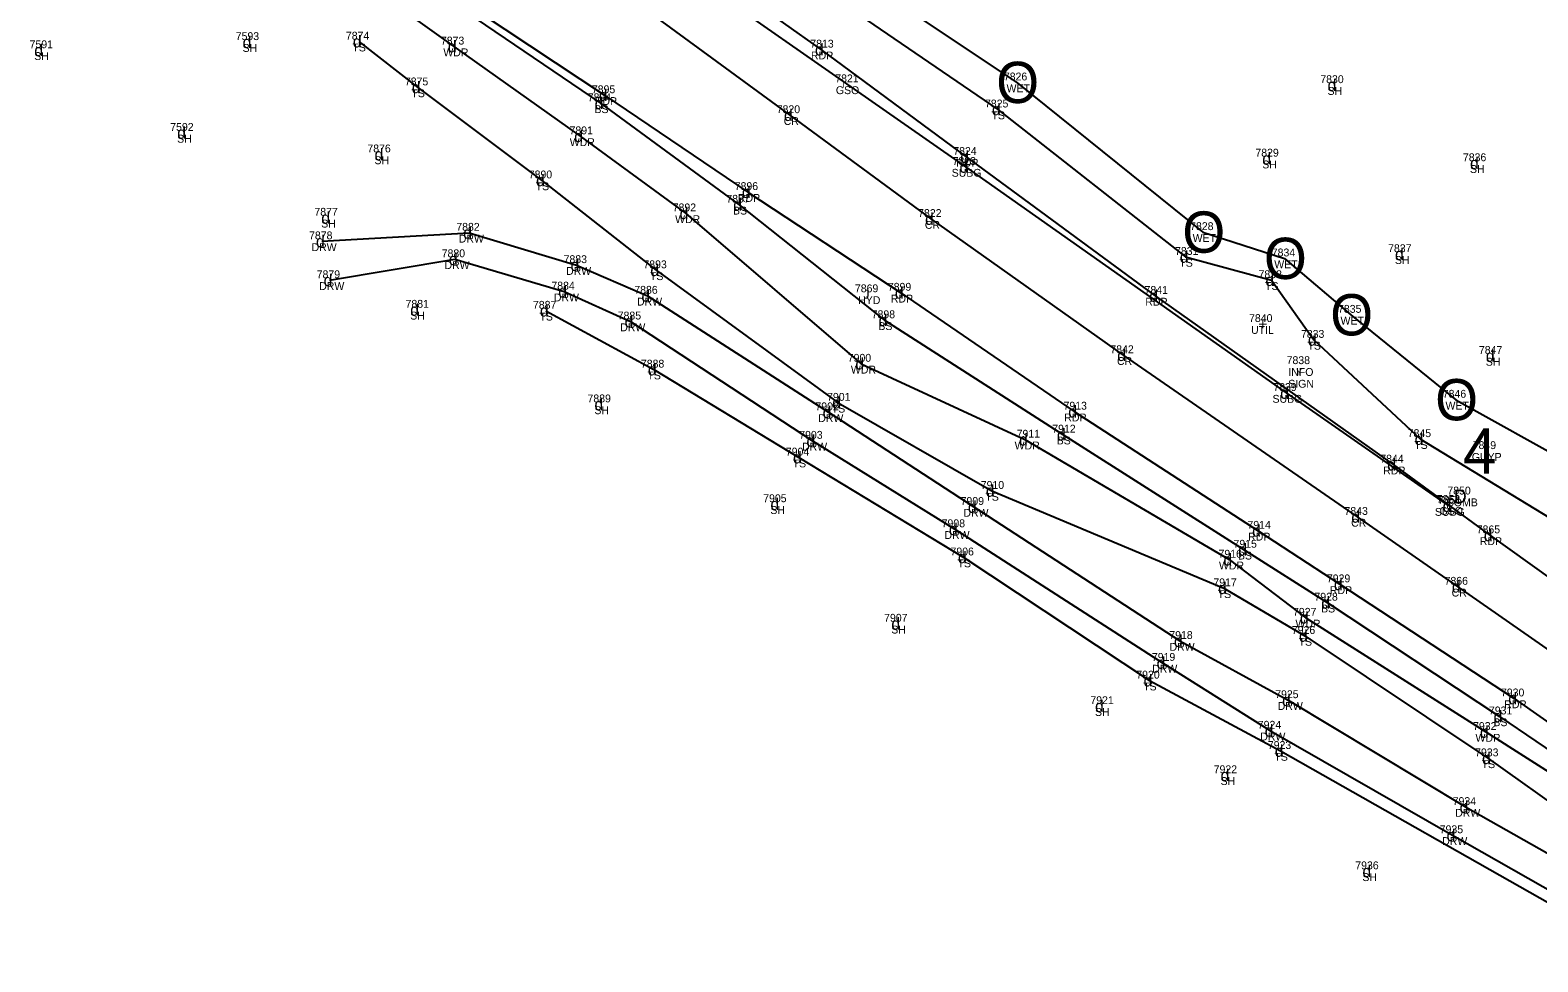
# Model space of a CAD drawing. Extents: x 69415 to 80913, y 7576 to 15059.
# Drawn here: x 76411 to 76794.6, y 13698.5 to 13935.5 of the extents above; entities that cross this region are included whole.
import ezdxf

# ---------------------------------------------------------------- set-up
doc = ezdxf.new("R2010")
doc.units = 0
for name, color, linetype in [('Level 11', 7, 'Continuous'), ('Level 14', 7, 'Continuous'), ('Level 15', 7, 'Continuous'), ('Level 16', 7, 'Continuous'), ('Level 43', 7, 'Continuous'), ('Level 46', 7, 'Continuous'), ('Level 47', 7, 'Continuous'), ('Level 48', 7, 'Continuous')]:
    doc.layers.add(name, color=color, linetype=linetype)

msp = doc.modelspace()

# ---------------------------------------------------------------- linework, layer by layer
at = {"layer": 'Level 11'}
for p, q in [((76582.3, 13951.78), (76612.2, 13930.52)), ((76525.54, 13939.89), (76557.19, 13918.92)), ((76612.2, 13930.52), (76649.16, 13903.23)), ((76557.19, 13918.92), (76593.6, 13894.29)), ((76649.16, 13903.23), (76697.27, 13867.89)), ((76593.6, 13894.29), (76632.52, 13868.69)), ((76485.23, 13881.76), (76522.7, 13883.94)), ((76522.7, 13883.94), (76550, 13875.72)), ((76487.18, 13871.87), (76519.06, 13877.21)), ((76519.06, 13877.21), (76546.89, 13868.98)), ((76550, 13875.72), (76568.05, 13867.92)), ((76546.89, 13868.98), (76563.77, 13861.38)), ((76568.05, 13867.92), (76614.16, 13838.29)), ((76632.52, 13868.69), (76676.65, 13838.45)), ((76697.27, 13867.89), (76757.81, 13824.97)), ((76563.77, 13861.38), (76610.04, 13831.04)), ((76614.16, 13838.29), (76651.11, 13814.22)), ((76676.65, 13838.45), (76723.44, 13808.15)), ((76610.04, 13831.04), (76646.28, 13808.55)), ((76757.81, 13824.97), (76782.39, 13807)), ((76651.11, 13814.22), (76703.55, 13780.12)), ((76646.28, 13808.55), (76699.14, 13774.56)), ((76723.44, 13808.15), (76744.24, 13794.54)), ((76782.39, 13807), (76823.24, 13777.86)), ((76744.24, 13794.54), (76788.61, 13765.52)), ((76703.55, 13780.12), (76731.07, 13765.08)), ((76699.14, 13774.56), (76726.64, 13757.31)), ((76788.61, 13765.52), (76830.09, 13736.38)), ((76731.07, 13765.08), (76776.24, 13737.9)), ((76726.64, 13757.31), (76772.93, 13730.73)), ((76776.24, 13737.9), (76817.02, 13714.92)), ((76772.93, 13730.73), (76825.9, 13700.66))]:
    msp.add_line(p, q, dxfattribs=at)
at = {"layer": 'Level 14'}
for p, q in [((76490.37, 13951.59), (76518.78, 13931.3)), ((76518.78, 13931.3), (76550.95, 13908.47)), ((76550.95, 13908.47), (76577.76, 13888.88)), ((76577.76, 13888.88), (76622.48, 13850.63)), ((76622.48, 13850.63), (76664.14, 13831.32)), ((76664.14, 13831.32), (76716.14, 13800.8)), ((76716.14, 13800.8), (76735.61, 13786.03)), ((76735.61, 13786.03), (76781.42, 13756.98)), ((76781.42, 13756.98), (76825.04, 13729.24))]:
    msp.add_line(p, q, dxfattribs=at)
at = {"layer": 'Level 15'}
for p, q in [((76579.01, 13949.56), (76648.98, 13900.68)), ((76648.98, 13900.68), (76730.6, 13843.2)), ((76730.6, 13843.2), (76771.92, 13814.45))]:
    msp.add_line(p, q, dxfattribs=at)
at = {"layer": 'Level 16'}
for p, q in [((76624.05, 13947.49), (76662.08, 13922.17)), ((76662.08, 13922.17), (76709.43, 13884.11)), ((76709.43, 13884.11), (76730.2, 13877.42)), ((76730.2, 13877.42), (76747.06, 13863.08)), ((76747.06, 13863.08), (76773.77, 13841.48)), ((76773.77, 13841.48), (76814.25, 13818.95))]:
    msp.add_line(p, q, dxfattribs=at)
at = {"layer": 'Level 48'}
for p, q in [((76524.52, 13938.36), (76556.15, 13916.87)), ((76570.47, 13938.61), (76604.32, 13913.85)), ((76620.31, 13940.48), (76657.22, 13915.3)), ((76494.6, 13932.55), (76509.61, 13920.91)), ((76509.61, 13920.91), (76541.23, 13897.26)), ((76556.15, 13916.87), (76591.41, 13891.07)), ((76657.22, 13915.3), (76705.02, 13877.8)), ((76604.32, 13913.85), (76640.22, 13887.44)), ((76541.23, 13897.26), (76570.31, 13874.4)), ((76591.41, 13891.07), (76628.4, 13861.7)), ((76640.22, 13887.44), (76689.13, 13852.81)), ((76705.02, 13877.8), (76726.83, 13871.89)), ((76570.31, 13874.4), (76616.57, 13840.7)), ((76726.83, 13871.89), (76737.63, 13856.71)), ((76542.2, 13864.11), (76569.67, 13849.15)), ((76628.4, 13861.7), (76673.78, 13832.61)), ((76737.63, 13856.71), (76764.79, 13831.47)), ((76689.13, 13852.81), (76748.69, 13811.69)), ((76569.67, 13849.15), (76606.62, 13826.77)), ((76616.57, 13840.7), (76655.67, 13818.29)), ((76673.78, 13832.61), (76719.9, 13803.34)), ((76764.79, 13831.47), (76808.58, 13804.75)), ((76606.62, 13826.77), (76648.58, 13801.37)), ((76655.67, 13818.29), (76714.78, 13793.54)), ((76748.69, 13811.69), (76774.27, 13793.92)), ((76648.58, 13801.37), (76695.81, 13770.05)), ((76719.9, 13803.34), (76741.05, 13789.87)), ((76714.78, 13793.54), (76735.36, 13781.41)), ((76774.27, 13793.92), (76815.39, 13765.17)), ((76741.05, 13789.87), (76784.89, 13760.95)), ((76735.36, 13781.41), (76781.94, 13750.29)), ((76695.81, 13770.05), (76729.2, 13752.16)), ((76784.89, 13760.95), (76827.05, 13732.12)), ((76729.2, 13752.16), (76823.78, 13698.53)), ((76781.94, 13750.29), (76820.72, 13722.63))]:
    msp.add_line(p, q, dxfattribs=at)

# ---------------------------------------------------------------- texts
at = {"layer": 'Level 15'}
for s, height, p in [('I', 1.7, (76617.71, 13920.84)), ('J', 2.26, (76623.05, 13867.17)), ('4', 11.5, (76775.59, 13822.67)), ('I', 1.7, (76771.34, 13813.86)), ('D', 3.4, (76773.26, 13815.17))]:
    msp.add_text(s, height=height, dxfattribs=at).set_placement(p)
at = {"layer": 'Level 16'}
for p in [(76656.83, 13916.92), (76704.18, 13878.86), (76724.95, 13872.17), (76741.81, 13857.83), (76768.52, 13836.23)]:
    msp.add_text('O', height=10.5, dxfattribs=at).set_placement(p)
at = {"layer": 'Level 43'}
msp.add_text('Y', height=1.7, dxfattribs=at).set_placement((76733.13, 13847.68))
at = {"layer": 'Level 46'}
for s, p in [('7593', (76463.31, 13932.93)), ('7874', (76491.34, 13933.05)), ('7591', (76410.86, 13930.86)), ('SH', (76465.06, 13929.93)), ('TS', (76493.01, 13930.05)), ('7873', (76515.52, 13931.8)), ('WDR', (76516.15, 13928.8)), ('7813', (76609.51, 13931.02)), ('SH', (76412.05, 13927.86)), ('RDP', (76609.69, 13928.02)), ('7875', (76506.35, 13921.41)), ('7821', (76615.87, 13922.19)), ('7826', (76658.77, 13922.67)), ('7830', (76739.29, 13921.99)), ('TS', (76508.02, 13918.41)), ('7894', (76552.89, 13917.37)), ('7895', (76553.93, 13919.42)), ('GSO', (76616.02, 13919.19)), ('WET', (76659.46, 13919.67)), ('SH', (76741.13, 13918.99)), ('BS', (76554.59, 13914.37)), ('RDP', (76554.68, 13916.42)), ('7820', (76600.97, 13914.35)), ('7825', (76653.96, 13915.8)), ('TS', (76655.63, 13912.8)), ('7592', (76446.65, 13909.85)), ('7891', (76548.25, 13908.97)), ('CR', (76602.75, 13911.35)), ('SH', (76448.4, 13906.85)), ('WDR', (76548.31, 13905.97)), ('7876', (76496.81, 13904.37)), ('SH', (76498.61, 13901.37)), ('7824', (76645.9, 13903.73)), ('7829', (76722.77, 13903.3)), ('7836', (76775.58, 13902.13)), ('7890', (76537.88, 13897.76)), ('SUBG', (76645.5, 13898.18)), ('7823', (76645.72, 13901.18)), ('RDP', (76646.64, 13900.73)), ('SH', (76724.52, 13900.3)), ('SH', (76777.38, 13899.13)), ('TS', (76539.64, 13894.76)), ('7896', (76590.28, 13894.79)), ('7897', (76588.15, 13891.57)), ('RDP', (76591.09, 13891.79)), ('7877', (76483.33, 13888.26)), ('7892', (76574.5, 13889.38)), ('WDR', (76575.12, 13886.38)), ('BS', (76589.85, 13888.57)), ('7822', (76636.96, 13887.94)), ('7878', (76481.97, 13882.26)), ('SH', (76485.08, 13885.26)), ('7882', (76519.44, 13884.44)), ('CR', (76638.66, 13884.94)), ('7828', (76706.17, 13884.61)), ('DRW', (76482.6, 13879.26)), ('DRW', (76520.07, 13881.44)), ('7831', (76702.32, 13878.3)), ('WET', (76706.81, 13881.61)), ('7837', (76756.54, 13879)), ('7880', (76515.72, 13877.71)), ('DRW', (76516.43, 13874.71)), ('7883', (76546.74, 13876.22)), ('7893', (76567.05, 13874.9)), ('TS', (76703.43, 13875.3)), ('7834', (76726.94, 13877.92)), ('WET', (76727.58, 13874.92)), ('SH', (76758.28, 13876)), ('7879', (76483.91, 13872.37)), ('DRW', (76547.37, 13873.22)), ('TS', (76568.72, 13871.9)), ('7832', (76723.57, 13872.39)), ('DRW', (76484.55, 13869.37)), ('7884', (76543.63, 13869.48)), ('7886', (76564.73, 13868.42)), ('7869', (76620.87, 13868.8)), ('7899', (76629.25, 13869.19)), ('7841', (76694.57, 13868.39)), ('TS', (76725.24, 13869.39)), ('7881', (76506.52, 13864.86)), ('7887', (76538.94, 13864.61)), ('DRW', (76544.26, 13866.48)), ('DRW', (76565.42, 13865.42)), ('HYD', (76621.7, 13865.8)), ('RDP', (76630.01, 13866.19)), ('RDP', (76694.76, 13865.39)), ('7835', (76743.8, 13863.58)), ('SH', (76507.7, 13861.86)), ('TS', (76540.61, 13861.61)), ('7885', (76560.51, 13861.88)), ('7898', (76625.14, 13862.2)), ('BS', (76626.84, 13859.2)), ('7840', (76721.16, 13861.23)), ('WET', (76744.44, 13860.58)), ('DRW', (76561.14, 13858.88)), ('UTIL', (76721.67, 13858.23)), ('7833', (76734.37, 13857.21)), ('7842', (76685.87, 13853.31)), ('TS', (76736.03, 13854.21)), ('7847', (76779.65, 13853.13)), ('7888', (76566.41, 13849.65)), ('7900', (76619.05, 13851.13)), ('WDR', (76619.84, 13848.13)), ('CR', (76687.56, 13850.31)), ('7838', (76730.72, 13850.53)), ('INFO', (76731.15, 13847.53)), ('SH', (76781.4, 13850.13)), ('TS', (76568.08, 13846.65)), ('7839', (76727.33, 13843.7)), ('SIGN', (76731.13, 13844.53)), ('7889', (76552.82, 13840.8)), ('7901', (76613.79, 13841.2)), ('SUBG', (76727.13, 13840.7)), ('7846', (76770.45, 13841.98)), ('SH', (76554.57, 13837.8)), ('7902', (76610.82, 13838.79)), ('TS', (76614.98, 13838.2)), ('7913', (76673.95, 13838.95)), ('WET', (76771.15, 13838.98)), ('DRW', (76611.53, 13835.79)), ('7912', (76671.08, 13833.11)), ('RDP', (76674.14, 13835.95)), ('7903', (76606.7, 13831.54)), ('DRW', (76607.41, 13828.54)), ('WDR', (76661.51, 13828.82)), ('7911', (76662.02, 13831.82)), ('BS', (76672.22, 13830.11)), ('7845', (76761.53, 13831.97)), ('TS', (76763.2, 13828.97)), ('7849', (76778.07, 13828.92)), ('7904', (76603.29, 13827.27)), ('7844', (76754.55, 13825.47)), ('GUYP', (76777.85, 13825.92)), ('TS', (76605.03, 13824.27)), ('RDP', (76755.3, 13822.47)), ('7910', (76652.89, 13818.79)), ('7850', (76771.62, 13817.37)), ('7905', (76597.53, 13815.42)), ('7909', (76647.77, 13814.72)), ('TS', (76654.08, 13815.79)), ('7852', (76768.93, 13815.21)), ('7851', (76769.22, 13814.95)), ('COMB', (76771.35, 13814.37)), ('SH', (76599.35, 13812.42)), ('DRW', (76648.48, 13811.72)), ('7843', (76745.44, 13812.19)), ('CR', (76747.13, 13809.19)), ('SUBG', (76768.45, 13811.95)), ('GSO', (76769.65, 13812.21)), ('7908', (76642.94, 13809.05)), ('DRW', (76643.65, 13806.05)), ('7914', (76720.75, 13808.65)), ('RDP', (76720.93, 13805.65)), ('7865', (76779.09, 13807.5)), ('7906', (76645.19, 13801.87)), ('7915', (76717.2, 13803.84)), ('RDP', (76779.88, 13804.5)), ('TS', (76646.99, 13798.87)), ('WDR', (76713.5, 13798.3)), ('7916', (76713.39, 13801.3)), ('BS', (76718.34, 13800.84)), ('7917', (76712.08, 13794.04)), ('7929', (76740.97, 13795.04)), ('7866', (76770.91, 13794.42)), ('TS', (76713.19, 13791.04)), ('7928', (76737.79, 13790.37)), ('RDP', (76741.73, 13792.04)), ('CR', (76772.7, 13791.42)), ('7927', (76732.35, 13786.53)), ('BS', (76739.49, 13787.37)), ('7907', (76628.3, 13785.02)), ('WDR', (76732.97, 13783.53)), ('SH', (76630.12, 13782.02)), ('7918', (76700.86, 13780.62)), ('7926', (76732.05, 13781.91)), ('TS', (76733.77, 13778.91)), ('7919', (76696.43, 13775.06)), ('DRW', (76700.92, 13777.62)), ('DRW', (76696.51, 13772.06)), ('7920', (76692.47, 13770.55)), ('TS', (76694.22, 13767.55)), ('7921', (76680.78, 13764.06)), ('7925', (76727.81, 13765.58)), ('7930', (76785.26, 13766.02)), ('SH', (76681.96, 13761.06)), ('DRW', (76728.44, 13762.58)), ('7931', (76782.19, 13761.45)), ('RDP', (76786.1, 13763.02)), ('7924', (76723.38, 13757.81)), ('7932', (76778.16, 13757.48)), ('BS', (76783.33, 13758.45)), ('DRW', (76724.01, 13754.81)), ('7923', (76725.94, 13752.66)), ('WDR', (76778.78, 13754.48)), ('TS', (76727.61, 13749.66)), ('7933', (76778.68, 13750.79)), ('TS', (76780.35, 13747.79)), ('7922', (76712.16, 13746.49)), ('SH', (76713.91, 13743.49)), ('7934', (76772.98, 13738.4)), ('DRW', (76773.61, 13735.4)), ('7935', (76769.67, 13731.23)), ('DRW', (76770.3, 13728.23)), ('7936', (76748.19, 13722.06)), ('SH', (76749.99, 13719.06))]:
    msp.add_text(s, height=2, dxfattribs=at).set_placement(p)
at = {"layer": 'Level 47'}
for s, p in [('d', (76465.07, 13930.93)), ('d', (76493.1, 13931.05)), ('d', (76412.06, 13928.86)), ('d', (76517.28, 13929.8)), ('d', (76610.7, 13929.02)), ('d', (76508.11, 13919.41)), ('d', (76741.14, 13919.99)), ('d', (76555.69, 13917.42)), ('d', (76554.65, 13915.37)), ('d', (76602.82, 13912.35)), ('d', (76655.72, 13913.8)), ('d', (76448.41, 13907.85)), ('d', (76549.45, 13906.97)), ('d', (76498.63, 13902.37)), ('d', (76647.66, 13901.73)), ('d', (76724.54, 13901.3)), ('d', (76777.39, 13900.13)), ('d', (76647.48, 13899.18)), ('d', (76539.73, 13895.76)), ('d', (76592.1, 13892.79)), ('d', (76589.91, 13889.57)), ('d', (76485.09, 13886.26)), ('d', (76576.26, 13887.38)), ('d', (76638.72, 13885.94)), ('d', (76521.2, 13882.44)), ('d', (76483.73, 13880.26)), ('d', (76517.56, 13875.71)), ('d', (76548.5, 13874.22)), ('d', (76703.52, 13876.3)), ('d', (76758.3, 13877)), ('d', (76485.68, 13870.37)), ('d', (76568.81, 13872.9)), ('d', (76725.33, 13870.39)), ('d', (76545.39, 13867.48)), ('d', (76566.55, 13866.42)), ('d', (76631.02, 13867.19)), ('d', (76695.77, 13866.39)), ('d', (76507.71, 13862.86)), ('d', (76540.7, 13862.61)), ('d', (76562.27, 13859.88)), ('d', (76626.9, 13860.2)), ('+', (76723.52, 13859.23)), ('d', (76736.13, 13855.21)), ('d', (76687.63, 13851.31)), ('d', (76781.41, 13851.13)), ('d', (76568.17, 13847.65)), ('d', (76620.98, 13849.13)), ('d', (76554.59, 13838.8)), ('d', (76615.07, 13839.2)), ('d', (76729.1, 13841.7)), ('d', (76612.66, 13836.79)), ('d', (76675.15, 13836.95)), ('d', (76672.28, 13831.11)), ('d', (76608.54, 13829.54)), ('d', (76662.64, 13829.82)), ('d', (76763.29, 13829.97)), ('d', (76605.12, 13825.27)), ('d', (76756.31, 13823.47)), ('d', (76654.17, 13816.79)), ('d', (76599.37, 13813.42)), ('d', (76649.61, 13812.72)), ('d', (76770.42, 13812.95)), ('d', (76747.19, 13810.19)), ('d', (76644.78, 13807.05)), ('d', (76721.94, 13806.65)), ('d', (76780.89, 13805.5)), ('d', (76718.4, 13801.84)), ('d', (76647.08, 13799.87)), ('d', (76714.64, 13799.3)), ('d', (76742.74, 13793.04)), ('d', (76713.28, 13792.04)), ('d', (76772.77, 13792.42)), ('d', (76739.55, 13788.37)), ('d', (76630.14, 13783.02)), ('d', (76734.11, 13784.53)), ('d', (76702.05, 13778.62)), ('d', (76733.86, 13779.91)), ('d', (76697.64, 13773.06)), ('d', (76694.31, 13768.55)), ('d', (76681.97, 13762.06)), ('d', (76729.57, 13763.58)), ('d', (76787.11, 13764.02)), ('d', (76783.39, 13759.45)), ('d', (76725.14, 13755.81)), ('d', (76779.92, 13755.48)), ('d', (76727.7, 13750.66)), ('d', (76780.44, 13748.79)), ('d', (76713.92, 13744.49)), ('d', (76774.74, 13736.4)), ('d', (76771.43, 13729.23)), ('d', (76750.01, 13720.06))]:
    msp.add_text(s, height=3, dxfattribs=at).set_placement(p)

doc.saveas('drawing.dxf')
